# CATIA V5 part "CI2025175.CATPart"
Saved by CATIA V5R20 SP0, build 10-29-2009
Part number: CI2025175
Bounding box of the stored display mesh (mm): x -24 to 24, y -18.97 to 209.5, z -32.903 to 26.909
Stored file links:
  C:\Users\Raffaele\Desktop\3D X SITO CF\BOLEX\19-INCLINED ASSEMBLY REF_CI\CI2025175.CATPart

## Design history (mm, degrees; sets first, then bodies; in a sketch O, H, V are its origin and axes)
Set1
  DatumSurface1 to DatumSurface16 "MANIFOLD_SOLID_BREP #393"
  DatumSurface17 to DatumSurface39 "MANIFOLD_SOLID_BREP #1138"
Body1 (main body)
